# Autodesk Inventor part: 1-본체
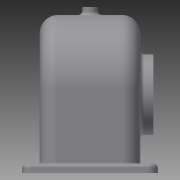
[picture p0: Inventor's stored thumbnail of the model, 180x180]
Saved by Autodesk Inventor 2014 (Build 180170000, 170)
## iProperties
Created: 2016-01
Part Number: 1-본체
Material: Generic
Document SubType Name: Modeling
Designer: KB20301
Density: 1 g/cm^3
Appearance: Default
Author: KB20301
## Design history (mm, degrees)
sketch "스케치1"
  geometry: L1 (-57, 0)-(-57, -57); L2 (-57, -57)-(57, -57); L3 (57, 0)-(57, -57); A1 r 57 centre (0, 0) between (57, 0) and (-57, 0); 1 further point
  constraints: 6 end point, 2 perpendicular, 2 point on circle, 2 tangent, 1 centre point, 1 coincident, 1 vertical
  dimensions: "d0" = 114 diameter of A1; "d1" = 57 distance from line of L2 point (0, 0)
extrude "돌출1" new body sketch "스케치1" stored distance "d2" = 77; taper "d3" = 0 deg
feature "쉘1" dims "d8" = 6, "d19" = 5
sketch "스케치3"
  geometry: L1 (108, -72)-(6, -72) reference; L2 (6, -72)-(6, -5) reference; L3 (6, -5)-(108, -5) reference; L4 (108, -5)-(108, -72) reference; L5 (127, 13.5)-(-13, 13.5); L6 (-13, 13.5)-(-13, -90.5); L7 (-13, -90.5)-(127, -90.5); L8 (127, -90.5)-(127, 13.5); L9 (127, 13.5)-(-13, -90.5); L10 (-13, 13.5)-(127, -90.5); 2 further points
  constraints: 12 end point, 2 midpoint, 2 parallel, 1 horizontal, 1 perpendicular
  dimensions: "d10" = 104 distance of L7.end L5.start; "d11" = 140 distance of L6.end L7.end
extrude "돌출3" join sketch "스케치3" distance "d12" = 7; taper "d13" = 0 deg
sketch "스케치4"
  geometry: L1 (70, -57)-(-70, -57) reference; L2 (70, -64)-(-70, -64) reference; C1 r 31 at (0, -4); A1 r 57 centre (0, 0) between (57, 0) and (-57, 0) reference
  constraints: 1 centre point, 1 vertical alignment
  dimensions: "d14" = 62 diameter of C1; "d16" = 60 distance from line of L2 C1.centre
extrude "돌출4" join sketch "스케치4" distance "d17" = 10; taper "d18" = 0 deg
sketch "스케치6"
  geometry: L1 (-4, -19.5)-(-4, -33.5); L2 (-64, 33.5)-(-64, -33.5) reference; L3 (0, -38.5)-(57, -38.5) reference; L4 (0, -33.5)-(51, -33.5) reference; L5 (-4, -19.5)-(24, -19.5); L6 (24, -19.5)-(35.747, -33.5); L7 (35.747, -33.5)-(-4, -33.5); 1 further point
  constraints: 8 end point, 1 parallel, 1 perpendicular, 1 vertical
  dimensions: "d20" = 60 distance between parallel lines of L2 L1; "d21" = 19 distance between parallel lines of L5 L3; "d22" = 14 distance between parallel lines of L5 L7; "d23" = 50 deg angle of L5 L6; "d24" = 56 diameter of L5.end L1
revolve "회전1" stored, may be unused: angle "d25" = 90 deg
sketch "스케치7"
  geometry: L1 (-4, -38.5)-(-4, -19.5); L2 (-64, 33.5)-(-64, -33.5) reference; L3 (0, -38.5)-(57, -38.5) reference; L4 (0, -38.5)-(-57, -38.5) reference; L5 (-4, -35.5)-(30.899, -35.5); L6 (-32, -19.5)-(24, -19.5) reference; L7 (-43.747, -33.5)-(35.747, -33.5) reference; L8 (24, -19.5)-(35.747, -33.5) reference; L9 (30.899, -35.5)-(33.416, -38.5); 1 further point
  constraints: 6 end point, 3 point on line, 2 parallel, 1 midpoint, 1 vertical
  dimensions: "d30" = 60 distance between parallel lines of L2 L1; "d31" = 3 distance between parallel lines of L5 L3; "d32" = 5 distance between parallel lines of L8 L9
revolve "회전2" sketch "스케치7" stored, may be unused: angle "d34" = 90 deg
sketch "스케치8"
  geometry: C1 r 34.899 at (0, 0) reference; C2 r 20 at (0, 0); A1 r 57 centre (0, 4) between (57, 4) and (-57, 4) reference
  constraints: 1 centre point, 1 coincident
  dimensions: "d36" = 40 diameter of C2
extrude "돌출5" cut sketch "스케치8" stored distance "d37" = 10; taper "d38" = 0 deg
sketch "스케치9"
  geometry: C1 r 31 at (0, 0) reference; C2 r 20 at (0, 0)
  constraints: 1 centre point, 1 coincident
  dimensions: "d39" = 40 diameter of C2
extrude "돌출6" cut sketch "스케치9" distance "d40" = 15; taper "d41" = 0 deg
node "작업 평면1"
sketch "스케치10"
  geometry: C1 r 6 at (-57, -38.5); 1 further point
  constraints: 1 centre point, 1 coincident
  dimensions: "d43" = 12 diameter of C1
extrude "돌출7" join sketch "스케치10" stored distance "d44" = 15; taper "d45" = 0 deg
hole "구멍1" diameter "d48" = 4.459; stored, may be unused: countersink angle "d52" = 90 deg, drill point angle "d54" = 118 deg; dims "d46" = 10, "d47" = 10, "d49" = 6, "d50" = 4, "d51" = 2, "d53" = 8
sketch "스케치12" dims "d55" = 48
  geometry: C1 r 20 at (0, 0) reference; C2 r 31 at (0, 0) reference; 2 further points
  constraints: 2 vertical alignment, 1 coincident, 2 other
hole "구멍2" sketch "스케치12" at (0, 24) diameter "d56" = 2.459; stored, may be unused: countersink angle "d60" = 90 deg, drill point angle "d62" = 118 deg; dims "d57" = 6, "d58" = 4, "d59" = 2, "d61" = 8
sketch "스케치13" dims "d66" = 56
  geometry: C1 r 20 at (0, 0) reference; C2 r 34.899 at (0, 0) reference; 2 further points
  constraints: 2 vertical alignment, 1 coincident, 2 other
hole "구멍3" sketch "스케치13" at (0, 28) diameter "d67" = 2.459; stored, may be unused: countersink angle "d71" = 90 deg, drill point angle "d73" = 118 deg; dims "d68" = 7, "d69" = 4, "d70" = 2, "d72" = 9
sketch "스케치14"
  geometry: L1 (127, 90.5)-(127, -13.5) reference; L2 (-13, 90.5)-(127, 90.5) reference; C1 r 2.5 at (119, 82.5); 1 further point
  constraints: 1 centre point
  dimensions: "d77" = 8 distance from line of L1 C1.centre; "d78" = 8 distance from line of C1.centre L2; "d79" = 5 diameter of C1
extrude "돌출8" cut sketch "스케치14" stored distance "d80" = 15; taper "d81" = 0 deg
fillet "모깎기1" dims "d88" = 8
fillet "모깎기2" dims "d89" = 9
fillet "모깎기3" dims "d90" = 14
fillet "모깎기4" dims "d91" = 3
fillet "모깎기5" dims "d92" = 3
fillet "모깎기6" dims "d93" = 1
fillet "모깎기7" dims "d94" = 3
node "작업 평면2"
sketch "스케치15"
  geometry: L1 (64, 44)-(64, -44) reference; 2 further points
  constraints: 1 horizontal alignment, 1 other
  dimensions: "d96" = 30 distance from line of L1 point (34, 0)
feature "엠보싱1" sketch "스케치15" dims "d97" = 0.5, "d98" = 0
chamfer "모따기1" distance "d99" = 1; stored, may be unused: second distance "d100" = 2, angle "d101" = 45 deg
chamfer "모따기2" distance "d102" = 1; stored, may be unused: second distance "d103" = 2, angle "d104" = 45 deg
fillet "모깎기8" dims "d105" = 3
node "솔리드1"
pattern_circular "원형 패턴1" dims angle "d64" = 360 deg
pattern_circular "원형 패턴2" dims angle "d75" = 360 deg
pattern_linear "직사각형 패턴1" dims "d84" = 88
pattern_linear "직사각형 패턴2" dims "d87" = 124
node "투영된 루프1"
other parameters: "d42" = -127
